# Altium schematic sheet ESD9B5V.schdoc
size 127 x 101 mm
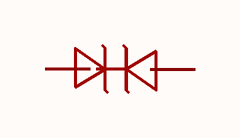
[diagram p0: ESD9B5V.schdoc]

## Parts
D?  esd9b5v  [SOD-923_L0.8-W0.6-LS1.0-BI-1]  (value not drawn)

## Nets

Not connected (* = marked no-connect by the designer): D? 1(C) 2(A)

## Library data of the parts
D? = esd9b5v: 极性:双向;反向截止电压(Vrwm):5V;钳位电压:10V;峰值脉冲电流(Ipp):8A@8/20us;峰值脉冲功率(Ppp):80W@8/20us;击穿电压:8.4V;; Manufacturer: TECH PUBLIC(台舟); AddInBom: yes; ModelId: 2f595e76c437472fa7f031dc65d7fe13; ModelTransform: 39.37,23.622,0,0,0,0,-0.005,0,0; Polarity: 双向; Reverse Stand-Off Voltage (Vrwm): 5V; Clamping Voltage: 10V; Voltage - Breakdown: 8.4V; Reverse Leakage Current (Ir): 80nA; Number of Channels: 单路; level of protection: IEC 61000-4-2；IEC 61000-4-5; Type: ESD; Junction Capacitance: 15pF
